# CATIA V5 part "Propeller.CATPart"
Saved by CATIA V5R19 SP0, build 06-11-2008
Part number: Propeller
Bounding box of the stored display mesh (mm): x -39.492 to 40, y -10 to 10, z -40 to 39.42
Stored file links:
  D:\Lectures\Catia DMU Lecture Notes\Practice Files\Revolute Joint\Electric Fan\Result\Electric Fan Assembly with No SubAssembly\Propeller.CATPart
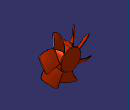
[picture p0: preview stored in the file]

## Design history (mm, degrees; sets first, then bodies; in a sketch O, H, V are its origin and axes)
Body1 (main body)
Body2 "Fan Propeller"
  Solid1 "Propeller": solid without history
